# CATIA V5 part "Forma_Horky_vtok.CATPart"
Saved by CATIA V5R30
Part number: Forma_Horky_vtok
Publications: "TapHole_CapScrew_E1200_2.3_", "TapHole_CapScrew_E1200_2.4_", "TapHole_CapScrew_E1200_3.1_", "TapHole_CapScrew_E1200_3.2_"
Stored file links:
  E:\Bakalarka\Model\Forma_v7\Forma_Horky_vtok.CATPart
  E:\Bakalarka\Model\Forma_v7\Forma.CATProduct
  E:\Bakalarka\Model\Forma_v7\TlgItf_Horky_vtok.CATProduct
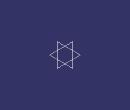
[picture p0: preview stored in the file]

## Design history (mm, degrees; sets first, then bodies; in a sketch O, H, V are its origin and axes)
Body1 (main body)
Body2 "TapHole"
  Solid1: linked copy from another document
Body3 "TapHole"
  Solid2: linked copy from another document
Body4 "TapHole"
  Solid3: linked copy from another document
Body5 "TapHole"
  Solid4: linked copy from another document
